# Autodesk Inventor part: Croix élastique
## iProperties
Shininess: 64.0
Length Units: 11269
Angle Units: 11279
Time Units: 11290
Mass Units: 11283
Length Display Precision: 3
Angle Display Precision: 2
Compacted: True
Part Number: Croix élastique
Document SubType Name: Modeling
Created: 2003-05
Material: Delrin - Noir
Designer: Philippe
Density: 0.0
Volumn: 0.0
Area: 0.0
PropertySet Name: Model Information
Control State: 0
Master: False
Checked Out: False
Author: Philippe
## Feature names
1. Extrusion1
2. Extrusion2
